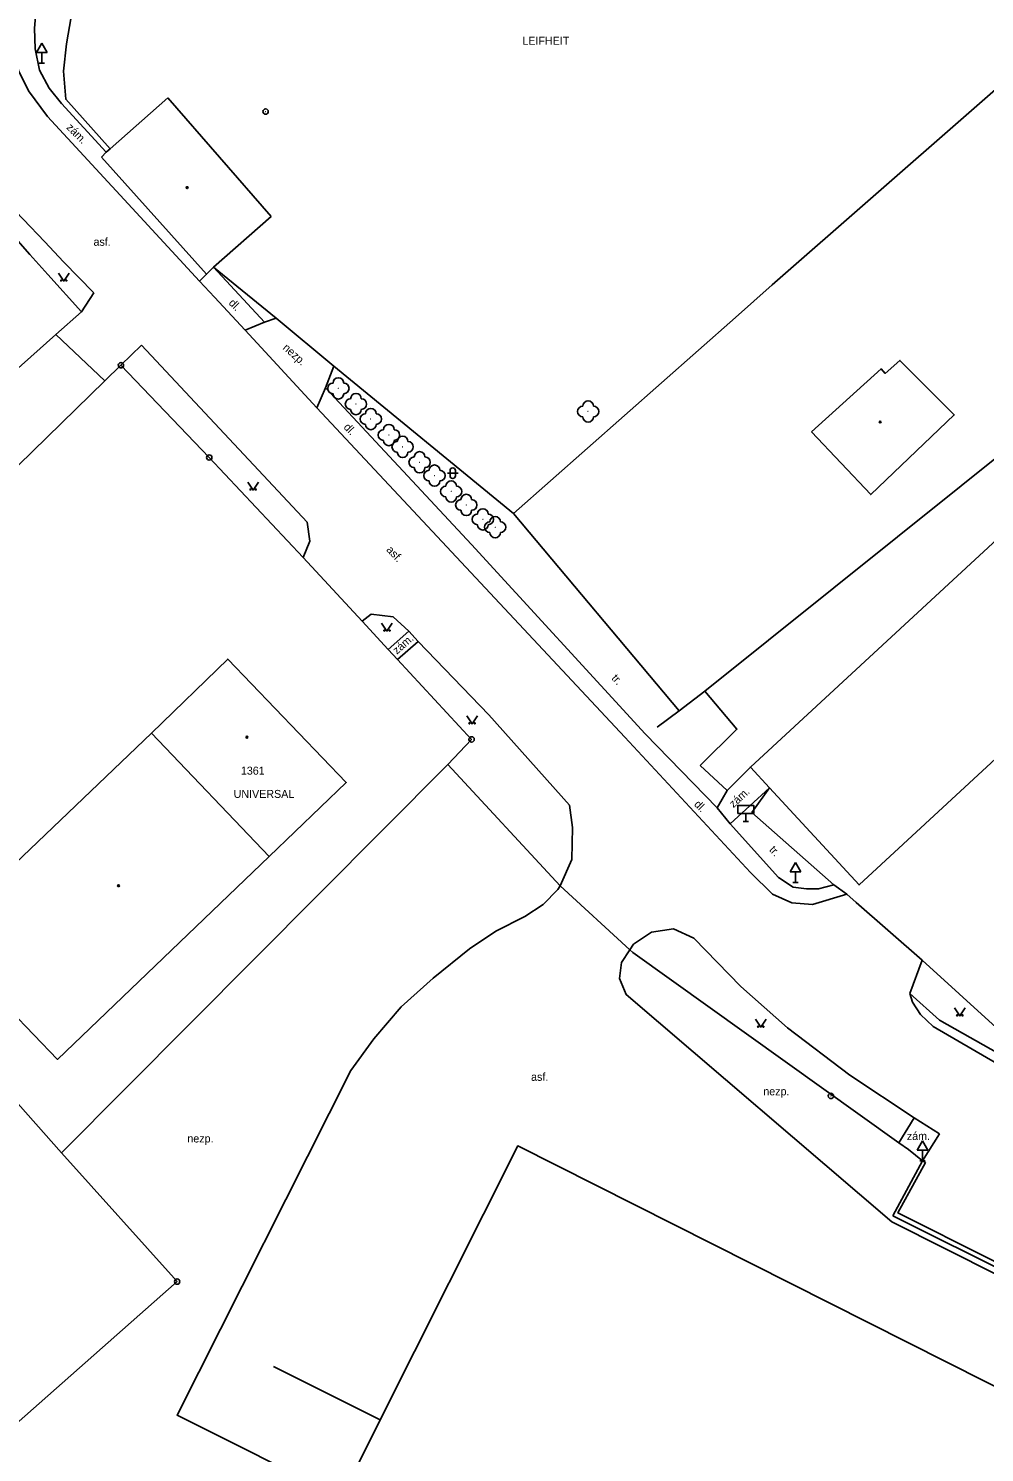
# Model space of a CAD drawing. Extents: x -794191 to -788944, y -1117087 to -1105044.
# Drawn here: x -792978.7 to -792889.1, y -1110562.8 to -1110429.3 of the extents above; entities that cross this region are included whole.
import ezdxf

# ---------------------------------------------------------------- set-up
doc = ezdxf.new("R2010")
doc.units = 0
for name, color, linetype in [('Doplněk polohopisu', 7, 'Continuous'), ('Doplňkové značky', 7, 'Continuous'), ('Hranice - ploty_ zdi', 7, 'Continuous'), ('Komunikace', 7, 'Continuous'), ('Pomocné popisy', 7, 'Continuous'), ('Popisy budov', 7, 'Continuous'), ('Stavební objekty', 7, 'Continuous'), ('temporary_level_1', 7, 'Continuous'), ('Zeleň', 7, 'Continuous'), ('Značky druhů budov', 7, 'Continuous'), ('Značky druhů pozemků', 7, 'Continuous'), ('Čísla popisná', 7, 'Continuous')]:
    doc.layers.add(name, color=color, linetype=linetype)

msp = doc.modelspace()

# ---------------------------------------------------------------- linework, layer by layer
at = {"layer": 'Doplněk polohopisu'}
for p, q in [((-792962.02, -1110452.31), (-792962.69, -1110452.96)), ((-792956.58, -1110456.81), (-792961.37, -1110451.64)), ((-792937.19, -1110477.63), (-792950.86, -1110462.95)), ((-792912.92, -1110503.82), (-792909.22, -1110500.46)), ((-792912.92, -1110503.82), (-792914.15, -1110502.32))]:
    msp.add_line(p, q, dxfattribs=at)
for points in [[(-792937.19, -1110477.63), (-792920.88, -1110495.38), (-792914.15, -1110502.32), (-792913.21, -1110500.69)], [(-792912.92, -1110503.82), (-792908.37, -1110508.87), (-792907.02, -1110509.77), (-792905.77, -1110509.93), (-792904.63, -1110509.93), (-792903.19, -1110509.54)], [(-792894.91, -1110516.6), (-792896.06, -1110519.73)], [(-792896.06, -1110519.73), (-792893.29, -1110522.23), (-792880.79, -1110529.3), (-792868.74, -1110535.58), (-792868.14, -1110534.46)], [(-792858.77, -1110550.83), (-792862.3, -1110557.81), (-792897.19, -1110540.31), (-792894.61, -1110535.58), (-792894.88, -1110535.42)]]:
    msp.add_lwpolyline(points, dxfattribs=at)
at = {"layer": 'Doplňkové značky'}
for p, q in [((-792977.46, -1110430.654), (-792977.96, -1110431.52)), ((-792977.46, -1110430.654), (-792976.96, -1110431.52)), ((-792977.96, -1110431.52), (-792976.96, -1110431.52)), ((-792977.71, -1110432.52), (-792977.21, -1110432.52)), ((-792977.46, -1110432.52), (-792977.46, -1110431.52)), ((-792911.46, -1110502.85), (-792911.46, -1110503.6)), ((-792911.71, -1110503.6), (-792911.21, -1110503.6)), ((-792906.8, -1110507.464), (-792907.3, -1110508.33)), ((-792906.8, -1110507.464), (-792906.3, -1110508.33)), ((-792907.3, -1110508.33), (-792906.3, -1110508.33)), ((-792906.8, -1110509.33), (-792906.8, -1110508.33)), ((-792907.05, -1110509.33), (-792906.55, -1110509.33)), ((-792894.88, -1110533.554), (-792895.38, -1110534.42)), ((-792894.88, -1110533.554), (-792894.38, -1110534.42)), ((-792895.38, -1110534.42), (-792894.38, -1110534.42)), ((-792895.13, -1110535.42), (-792894.63, -1110535.42)), ((-792894.88, -1110535.42), (-792894.88, -1110534.42))]:
    msp.add_line(p, q, dxfattribs=at)
msp.add_lwpolyline([(-792912.21, -1110502.85), (-792910.71, -1110502.85), (-792910.71, -1110502.1), (-792912.21, -1110502.1)], close=True, dxfattribs=at)
at = {"layer": 'Hranice - ploty_ zdi'}
for p, q in [((-792912.41, -1110456.36), (-792908.97, -1110453.31)), ((-792971.56, -1110462.31), (-792976.14, -1110457.97)), ((-792961.77, -1110469.49), (-792970.05, -1110460.84)), ((-792952.96, -1110478.86), (-792961.77, -1110469.49)), ((-792947.44, -1110484.84), (-792952.96, -1110478.86)), ((-792945, -1110487.49), (-792947.44, -1110484.84)), ((-792944.1, -1110488.42), (-792945, -1110487.49)), ((-792937.16, -1110495.91), (-792944.1, -1110488.42)), ((-792939.39, -1110498.28), (-792937.16, -1110495.91)), ((-792939.39, -1110498.28), (-792975.63, -1110534.68)), ((-792928.86, -1110509.63), (-792939.39, -1110498.28)), ((-792915.74, -1110498.37), (-792913.21, -1110500.69)), ((-792913.21, -1110500.69), (-792911.02, -1110498.51)), ((-792909.22, -1110500.46), (-792910.9, -1110502.76)), ((-792910.9, -1110502.76), (-792903.19, -1110509.54)), ((-792901.09, -1110511.21), (-792894.91, -1110516.6)), ((-792896.21, -1110534.36), (-792897.1, -1110533.72)), ((-792964.78, -1110546.74), (-792975.63, -1110534.68)), ((-792897.65, -1110540.57), (-792894.88, -1110535.42)), ((-792862.12, -1110558.35), (-792897.65, -1110540.57)), ((-792955.74, -1110554.7), (-792945.75, -1110559.71))]:
    msp.add_line(p, q, dxfattribs=at)
for points in [[(-792946.14, -1110398.8), (-792959.21, -1110411.27), (-792973.68, -1110425.76), (-792974.71, -1110428.18), (-792975.14, -1110430.71), (-792975.43, -1110433.28), (-792975.23, -1110435.9), (-792971.06, -1110440.54)], [(-792881.05, -1110428.9), (-792908.97, -1110453.31)], [(-792915.29, -1110491.39), (-792861.09, -1110447.98)], [(-792961.37, -1110451.64), (-792955.49, -1110456.42), (-792950.07, -1110460.94), (-792933.23, -1110474.73)], [(-792912.41, -1110456.36), (-792933.23, -1110474.73), (-792917.7, -1110493.25)], [(-792970.05, -1110460.84), (-792971.56, -1110462.31), (-793008.12, -1110498)], [(-792975.63, -1110534.68), (-793008.12, -1110498), (-793024.36, -1110479.88), (-793050.07, -1110505.12), (-793051.53, -1110506.5)], [(-792919.76, -1110494.78), (-792917.7, -1110493.25), (-792915.29, -1110491.39), (-792912.29, -1110494.97), (-792915.74, -1110498.37)], [(-792922.06, -1110515.88), (-792922.33, -1110515.63), (-792928.86, -1110509.63)], [(-792903.19, -1110509.54), (-792901.98, -1110510.42), (-792901.09, -1110511.21)], [(-792897.1, -1110533.72), (-792922.06, -1110515.88)], [(-792894.91, -1110516.6), (-792884.49, -1110526.09), (-792868.14, -1110534.46)], [(-792894.88, -1110535.42), (-792896.21, -1110534.36)], [(-793071.87, -1110640.8), (-792993.06, -1110571.69), (-792986.91, -1110566.27), (-792964.78, -1110546.74)]]:
    msp.add_lwpolyline(points, dxfattribs=at)
at = {"layer": 'Komunikace'}
for p, q in [((-792981.24, -1110445.03), (-792977.17, -1110449.27)), ((-792972.58, -1110454.04), (-792973.75, -1110455.84)), ((-792956.58, -1110456.81), (-792955.49, -1110456.42)), ((-792958.4, -1110457.54), (-792956.58, -1110456.81)), ((-792968.12, -1110458.95), (-792970.05, -1110460.84)), ((-792952.6, -1110475.56), (-792968.12, -1110458.95)), ((-792950.86, -1110462.95), (-792950.07, -1110460.94)), ((-792950.86, -1110462.95), (-792951.68, -1110464.82)), ((-792943.06, -1110485.78), (-792944.53, -1110484.42)), ((-792945, -1110487.49), (-792943.06, -1110485.78)), ((-792942.17, -1110486.74), (-792943.06, -1110485.78)), ((-792944.1, -1110488.42), (-792942.17, -1110486.74)), ((-792935.54, -1110493.62), (-792942.17, -1110486.74)), ((-792928, -1110502.07), (-792935.54, -1110493.62)), ((-792921.99, -1110515.12), (-792922.33, -1110515.63)), ((-792911.91, -1110519.07), (-792916.31, -1110514.54)), ((-792922.33, -1110515.63), (-792923.11, -1110516.82)), ((-792907.53, -1110522.94), (-792911.91, -1110519.07)), ((-792901.71, -1110527.39), (-792907.53, -1110522.94)), ((-792895.66, -1110531.39), (-792901.71, -1110527.39)), ((-792897.1, -1110533.72), (-792895.66, -1110531.39)), ((-792895.66, -1110531.39), (-792893.28, -1110532.88)), ((-792894.88, -1110535.42), (-792893.28, -1110532.88))]:
    msp.add_line(p, q, dxfattribs=at)
for points in [[(-792958.4, -1110457.54), (-792961.28, -1110454.47), (-792962.69, -1110452.96), (-792968.99, -1110446.12), (-792976.95, -1110437.51), (-792978.73, -1110435.13), (-792979.64, -1110433.21), (-792979.91, -1110431.28), (-792979.96, -1110429.27), (-792979.78, -1110427.28), (-792979.37, -1110425.29), (-792978.7, -1110423.37), (-792978, -1110422.55), (-792970.96, -1110416.18), (-792961.55, -1110407.67), (-792949.19, -1110396.59), (-792943.12, -1110391.11), (-792934.93, -1110383.7), (-792934.06, -1110383.12), (-792933.17, -1110383.06), (-792932.09, -1110383.27)], [(-792971.42, -1110440.87), (-792975.63, -1110436.31), (-792976.78, -1110434.86), (-792977.7, -1110433.17), (-792978.08, -1110431.17), (-792978.14, -1110429.25), (-792978, -1110427.4), (-792977.65, -1110425.68), (-792976.9, -1110423.83), (-792970, -1110417.47), (-792960.59, -1110409.01), (-792948.07, -1110397.76), (-792946.14, -1110398.8)], [(-792977.17, -1110449.27), (-792975.45, -1110451.13), (-792972.58, -1110454.04)], [(-792958.4, -1110457.54), (-792951.68, -1110464.82), (-792922.79, -1110495.69)], [(-792952.96, -1110478.86), (-792952.35, -1110477.33), (-792952.6, -1110475.56)], [(-792947.44, -1110484.84), (-792946.58, -1110484.18), (-792944.53, -1110484.42)], [(-792922.79, -1110495.69), (-792911.02, -1110508.4), (-792908.96, -1110510.41), (-792907.15, -1110511.24), (-792905.21, -1110511.4), (-792901.98, -1110510.42)], [(-792928, -1110502.07), (-792927.69, -1110504.16), (-792927.78, -1110507.18), (-792928.86, -1110509.63), (-792929.09, -1110509.98), (-792930.45, -1110511.4), (-792932.17, -1110512.51), (-792934.88, -1110513.89), (-792937.36, -1110515.54), (-792940.78, -1110518.29), (-792943.76, -1110521), (-792946.34, -1110523.99), (-792948.48, -1110526.95), (-792964.79, -1110559.27), (-792949.38, -1110566.97)], [(-792916.31, -1110514.54), (-792918.23, -1110513.67), (-792920.28, -1110513.97), (-792921.99, -1110515.12)], [(-792923.11, -1110516.82), (-792923.29, -1110518.32), (-792922.66, -1110519.83), (-792897.75, -1110541.15), (-792862.84, -1110558.69), (-792848.18, -1110567.16)], [(-792867.49, -1110535.78), (-792868.92, -1110536.39), (-792880, -1110530.63), (-792887.91, -1110526.29), (-792893.89, -1110522.82), (-792895.07, -1110521.69), (-792895.82, -1110520.55), (-792896.06, -1110519.73)]]:
    msp.add_lwpolyline(points, dxfattribs=at)
at = {"layer": 'Stavební objekty'}
for p in [(-792971.06, -1110440.54), (-792955.97, -1110446.9)]:
    msp.add_line(p, (-792965.66, -1110435.78), dxfattribs=at)
for points in [[(-792971.06, -1110440.54), (-792971.42, -1110440.87), (-792971.88, -1110441.32)], [(-792971.88, -1110441.32), (-792962.02, -1110452.31), (-792961.37, -1110451.64), (-792955.97, -1110446.9)], [(-793014.31, -1110474.73), (-792981.97, -1110446.66), (-792978.58, -1110450.45), (-792976.89, -1110452.34), (-792973.75, -1110455.84), (-792976.14, -1110457.97), (-793005.76, -1110484.37)], [(-792956.15, -1110506.89), (-792975.99, -1110525.92), (-792987.14, -1110514.35), (-792967.17, -1110495.32)], [(-792852.37, -1110574.57), (-792932.83, -1110534.03), (-792945.75, -1110559.71), (-792949.38, -1110566.97)]]:
    msp.add_lwpolyline(points, dxfattribs=at)
for points in [[(-792860.25, -1110451.6), (-792850.05, -1110462.63), (-792900.83, -1110509.55), (-792909.22, -1110500.46), (-792911.02, -1110498.51)], [(-792905.3, -1110467.08), (-792899.73, -1110472.97), (-792891.91, -1110465.5), (-792897, -1110460.39), (-792898.38, -1110461.61), (-792898.76, -1110461.17)], [(-792967.17, -1110495.32), (-792960.03, -1110488.39), (-792948.92, -1110499.94), (-792956.15, -1110506.89)]]:
    msp.add_lwpolyline(points, close=True, dxfattribs=at)
at = {"layer": 'temporary_level_1'}
for centre, radius in [((-792956.48, -1110437.06), 0.25), ((-792956.48, -1110437.06), 0.0005), ((-792970.05, -1110460.84), 0.25), ((-792970.05, -1110460.84), 0.0005), ((-792961.77, -1110469.49), 0.25), ((-792961.77, -1110469.49), 0.0005), ((-792937.16, -1110495.91), 0.25), ((-792937.16, -1110495.91), 0.0005), ((-792903.47, -1110529.34), 0.25), ((-792903.47, -1110529.34), 0.0005), ((-792964.78, -1110546.74), 0.25), ((-792964.78, -1110546.74), 0.0005)]:
    msp.add_circle(centre, radius, dxfattribs=at)
at = {"layer": 'Zeleň'}
for centre in [(-792949.66, -1110463.01), (-792948.01, -1110464.48), (-792946.62, -1110465.88), (-792926.24, -1110465.17), (-792944.92, -1110467.38), (-792943.63, -1110468.49), (-792942.04, -1110469.94), (-792940.64, -1110471.19), (-792939.08, -1110472.67), (-792937.66, -1110473.94), (-792936.11, -1110475.29), (-792934.95, -1110476.02)]:
    msp.add_circle(centre, 0.0005, dxfattribs=at)
for centre, start, end in [((-792949.66, -1110462.51), 0, 179.99999), ((-792950.16, -1110463.01), 89.99999, 269.99999), ((-792949.16, -1110463.01), 270, 89.99999), ((-792949.66, -1110463.51), 179.99999, 359.99999), ((-792948.51, -1110464.48), 89.99999, 269.99999), ((-792948.01, -1110463.98), 0, 179.99999), ((-792947.51, -1110464.48), 270, 89.99999), ((-792926.74, -1110465.17), 89.99999, 269.99999), ((-792926.24, -1110464.67), 0, 179.99999), ((-792925.74, -1110465.17), 270, 89.99999), ((-792948.01, -1110464.98), 179.99999, 359.99999), ((-792947.12, -1110465.88), 89.99999, 269.99999), ((-792946.62, -1110465.38), 0, 179.99999), ((-792946.12, -1110465.88), 270, 89.99999), ((-792926.24, -1110465.67), 179.99999, 359.99999), ((-792946.62, -1110466.38), 179.99999, 359.99999), ((-792945.42, -1110467.38), 89.99999, 269.99999), ((-792944.92, -1110466.88), 0, 179.99999), ((-792944.42, -1110467.38), 270, 89.99999), ((-792944.92, -1110467.88), 179.99999, 359.99999), ((-792944.13, -1110468.49), 89.99999, 269.99999), ((-792943.63, -1110467.99), 0, 179.99999), ((-792943.13, -1110468.49), 270, 89.99999), ((-792943.63, -1110468.99), 179.99999, 359.99999), ((-792942.54, -1110469.94), 89.99999, 269.99999), ((-792942.04, -1110469.44), 0, 179.99999), ((-792941.54, -1110469.94), 270, 89.99999), ((-792942.04, -1110470.44), 179.99999, 359.99999), ((-792941.14, -1110471.19), 89.99999, 269.99999), ((-792940.64, -1110470.69), 0, 179.99999), ((-792940.14, -1110471.19), 270, 89.99999), ((-792940.64, -1110471.69), 179.99999, 359.99999), ((-792939.58, -1110472.67), 89.99999, 269.99999), ((-792939.08, -1110472.17), 0, 179.99999), ((-792938.58, -1110472.67), 270, 89.99999), ((-792939.08, -1110473.17), 179.99999, 359.99999), ((-792938.16, -1110473.94), 89.99999, 269.99999), ((-792937.66, -1110473.44), 0, 179.99999), ((-792937.16, -1110473.94), 270, 89.99999), ((-792937.66, -1110474.44), 179.99999, 359.99999), ((-792936.61, -1110475.29), 89.99999, 269.99999), ((-792936.11, -1110474.79), 0, 179.99999), ((-792935.61, -1110475.29), 270, 89.99999), ((-792934.95, -1110475.52), 0, 179.99999), ((-792936.11, -1110475.79), 179.99999, 359.99999), ((-792935.45, -1110476.02), 89.99999, 269.99999), ((-792934.95, -1110476.52), 179.99999, 359.99999), ((-792934.45, -1110476.02), 270, 89.99999)]:
    msp.add_arc(centre, 0.5, start, end, dxfattribs=at)
at = {"layer": 'Značky druhů budov'}
for centre in [(-792963.84, -1110444.19), (-792898.85, -1110466.16), (-792958.23, -1110495.71), (-792970.27, -1110509.63)]:
    msp.add_circle(centre, 0.0875, dxfattribs=at)
at = {"layer": 'Značky druhů pozemků'}
for p, q in [((-792939.44, -1110470.96), (-792938.44, -1110470.96)), ((-792939.19, -1110471.21), (-792939.19, -1110470.71)), ((-792938.69, -1110471.21), (-792938.69, -1110470.71))]:
    msp.add_line(p, q, dxfattribs=at)
for points in [[(-792975.91, -1110452.2), (-792975.41, -1110452.95), (-792974.91, -1110452.2)], [(-792958.15, -1110471.79), (-792957.65, -1110472.54), (-792957.15, -1110471.79)], [(-792945.6, -1110485.01), (-792945.1, -1110485.76), (-792944.6, -1110485.01)], [(-792937.62, -1110493.71), (-792937.12, -1110494.46), (-792936.62, -1110493.71)], [(-792910.55, -1110522.14), (-792910.05, -1110522.89), (-792909.55, -1110522.14)], [(-792891.88, -1110521.08), (-792891.38, -1110521.83), (-792890.88, -1110521.08)]]:
    msp.add_lwpolyline(points, dxfattribs=at)
for centre in [(-792975.66, -1110452.9), (-792975.16, -1110452.9), (-792957.9, -1110472.49), (-792957.4, -1110472.49), (-792945.35, -1110485.71), (-792944.85, -1110485.71), (-792937.37, -1110494.41), (-792936.87, -1110494.41), (-792891.63, -1110521.78), (-792891.13, -1110521.78), (-792910.3, -1110522.84), (-792909.8, -1110522.84)]:
    msp.add_circle(centre, 0.05, dxfattribs=at)
for centre, start, end in [((-792938.94, -1110470.71), 0, 179.99999), ((-792938.94, -1110471.21), 179.99999, 359.99999)]:
    msp.add_arc(centre, 0.25, start, end, dxfattribs=at)

# ---------------------------------------------------------------- texts
at = {"layer": 'Pomocné popisy'}
for s, p in [('LEIFHEIT', (-792932.405, -1110430.799)), ('asf.', (-792972.62, -1110449.64)), ('asf.', (-792931.59, -1110527.92)), ('nezp.', (-792909.81, -1110529.28)), ('zám.', (-792896.35, -1110533.47)), ('nezp.', (-792963.82, -1110533.7))]:
    msp.add_text(s, height=0.75, dxfattribs=at).set_placement(p)
for s, rotation, p in [('zám.', 315, (-792975.215, -1110438.611)), ('dl.', 315.57484, (-792960.001, -1110455.067)), ('nezp.', 318.23254, (-792954.928, -1110459.282)), ('dl.', 314.11989, (-792949.222, -1110466.699)), ('asf.', 313.11673, (-792945.21, -1110478.18)), ('zám.', 41.03847, (-792944.17, -1110487.98)), ('tr.', 312.57907, (-792924.09, -1110490.22)), ('zám.', 42.62939, (-792912.61, -1110502.37)), ('dl.', 314.11989, (-792916.36, -1110502.05)), ('tr.', 312.01854, (-792909.31, -1110506.3))]:
    msp.add_text(s, height=0.75, rotation=rotation, dxfattribs=at).set_placement(p)
at = {"layer": 'Popisy budov'}
msp.add_text('UNIVERSAL', height=0.75, dxfattribs=at).set_placement((-792959.48, -1110501.4))
at = {"layer": 'Čísla popisná'}
msp.add_text('1361', height=0.75, dxfattribs=at).set_placement((-792958.8, -1110499.22))

doc.saveas('drawing.dxf')
